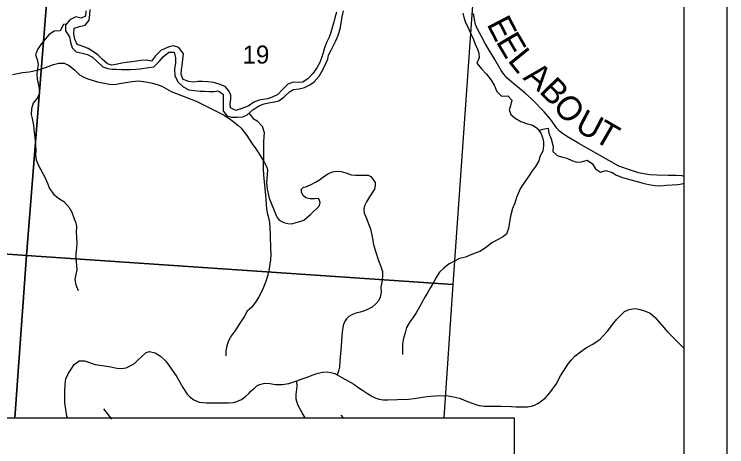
# Model space of a CAD drawing. Extents: x 0 to 34, y 0 to 22.
# Drawn here: x 28.762 to 30.417, y 18.393 to 19.396 of the extents above; entities that cross this region are included whole.
import ezdxf

# ---------------------------------------------------------------- set-up
doc = ezdxf.new("R2010")
doc.units = 0
for name, color, linetype in [('GM_X_County_Road', 7, 'Continuous'), ('GM_X_County_Road_Text', 7, 'Continuous'), ('GM_X_Major_River', 7, 'Continuous'), ('GM_X_Minor_River', 7, 'Continuous'), ('GM_X_Section', 7, 'Continuous'), ('GM_X_Section_Text', 7, 'Continuous'), ('GM_X_Township_Road', 7, 'Continuous'), ('SH_Data', 7, 'Continuous')]:
    doc.layers.add(name, color=color, linetype=linetype)

msp = doc.modelspace()

# ---------------------------------------------------------------- linework, layer by layer
at = {"layer": 'GM_X_County_Road'}
msp.add_lwpolyline([(30.3167, 19.0197), (30.313, 19.0211), (30.2994, 19.0221), (30.2811, 19.022), (30.2546, 19.023), (30.2382, 19.0237), (30.2238, 19.0261), (30.2119, 19.0284), (30.1928, 19.0342), (30.1663, 19.0437), (30.0735, 19.0965), (30.0449, 19.1136), (30.0355, 19.1192), (30.028, 19.1251), (30.0225, 19.1317), (30.0075, 19.1531), (29.9928, 19.1702), (29.9641, 19.1996), (29.9484, 19.2135), (29.922, 19.2351), (29.9071, 19.2477), (29.8991, 19.2573), (29.8929, 19.2656), (29.8782, 19.291), (29.8559, 19.3281), (29.8471, 19.3443), (29.8378, 19.3614), (29.8335, 19.3724), (29.831, 19.3846), (29.8284, 19.3983)], dxfattribs=at)
at = {"layer": 'GM_X_Major_River'}
for points in [[(29.5013, 19.3676), (29.4971, 19.3536), (29.4933, 19.3433), (29.488, 19.3323), (29.4827, 19.3187), (29.4793, 19.3065), (29.4759, 19.2955), (29.4717, 19.2841), (29.4652, 19.272), (29.4557, 19.2591), (29.4451, 19.2469), (29.4326, 19.239), (29.4231, 19.2382), (29.4102, 19.2386), (29.3973, 19.2341), (29.3844, 19.2212), (29.3741, 19.2102), (29.3597, 19.2034), (29.3502, 19.2), (29.3403, 19.1988), (29.3309, 19.1969), (29.3183, 19.192), (29.3054, 19.1833), (29.291, 19.1772), (29.277, 19.1731), (29.2644, 19.1788), (29.2637, 19.1894), (29.2652, 19.1989), (29.2652, 19.2084), (29.2607, 19.2183), (29.252, 19.2285), (29.2383, 19.2342), (29.225, 19.2377), (29.2117, 19.2392), (29.1996, 19.24), (29.1894, 19.24), (29.1776, 19.2389), (29.1673, 19.24), (29.1544, 19.245), (29.1499, 19.2563), (29.151, 19.2681), (29.1518, 19.2776), (29.1541, 19.2913), (29.1549, 19.3045), (29.1446, 19.319), (29.1321, 19.3228), (29.1219, 19.3209), (29.1124, 19.3171), (29.1029, 19.3118), (29.0904, 19.3001), (29.0812, 19.2875), (29.0683, 19.2894), (29.0558, 19.2891), (29.046, 19.2872), (29.0357, 19.2857), (29.022, 19.2846), (29.0118, 19.2831), (29.0019, 19.2808), (28.9887, 19.2781), (28.9788, 19.2812), (28.9667, 19.2918), (28.956, 19.3021), (28.9462, 19.3089), (28.934, 19.3165), (28.92, 19.3219), (28.9086, 19.326), (28.9029, 19.3382), (28.901, 19.35), (28.9011, 19.3636), (28.914, 19.3678), (28.9272, 19.3708), (28.9364, 19.3826), (28.9379, 19.3955), (28.9386, 19.4076)], [(28.9288, 19.4042), (28.9276, 19.3921), (28.9174, 19.3868), (28.9052, 19.3902), (28.8916, 19.383), (28.8813, 19.3709), (28.8813, 19.358), (28.8904, 19.3439), (28.8927, 19.3314), (28.8969, 19.3185), (28.9063, 19.3093), (28.9196, 19.3063), (28.9321, 19.3029), (28.9439, 19.2964), (28.9541, 19.2873), (28.9682, 19.2744), (28.9792, 19.2702), (28.9898, 19.2686), (28.9993, 19.2686), (29.011, 19.2679), (29.0213, 19.2679), (29.0311, 19.2682), (29.0444, 19.269), (29.0539, 19.2693), (29.0744, 19.2724), (29.0862, 19.2746), (29.0987, 19.2868), (29.1086, 19.2985), (29.1211, 19.308), (29.1336, 19.308), (29.1366, 19.2951), (29.1363, 19.2833), (29.1344, 19.2689), (29.1351, 19.2537), (29.1427, 19.2385), (29.1548, 19.2275), (29.1677, 19.221), (29.1943, 19.218), (29.2038, 19.2176), (29.214, 19.2172), (29.2261, 19.2172), (29.236, 19.2187), (29.247, 19.2111), (29.247, 19.1955), (29.2474, 19.1837), (29.2474, 19.172), (29.2557, 19.1606), (29.2667, 19.1575), (29.2796, 19.1571), (29.2929, 19.1579), (29.3028, 19.1632), (29.3164, 19.1746), (29.3301, 19.184), (29.3422, 19.1882), (29.3529, 19.1905), (29.3669, 19.1927), (29.3764, 19.1954), (29.3893, 19.2045), (29.4011, 19.2162), (29.4109, 19.2215), (29.4238, 19.2234), (29.4364, 19.2261), (29.4489, 19.2321), (29.4587, 19.2397), (29.4705, 19.2526), (29.4793, 19.2685), (29.4846, 19.2803), (29.4903, 19.2917), (29.4922, 19.3016), (29.4979, 19.3133), (29.5036, 19.3239), (29.5089, 19.3349), (29.5138, 19.3452), (29.5169, 19.3547), (29.5195, 19.3657), (29.521, 19.3763), (29.5233, 19.3904), (29.5264, 19.4044)], [(29.5104, 19.4014), (29.507, 19.3881), (29.5044, 19.3778), (29.5013, 19.3676)]]:
    msp.add_lwpolyline(points, dxfattribs=at)
at = {"layer": 'GM_X_Minor_River'}
msp.add_line((29.527, 18.4595), (29.521, 18.4659), dxfattribs=at)
for points in [[(29.8035, 19.3987), (29.8062, 19.3892), (29.8092, 19.3797), (29.8157, 19.3661), (29.8233, 19.3494), (29.8286, 19.3376), (29.8328, 19.327), (29.8377, 19.3153), (29.8408, 19.3058), (29.8415, 19.2952), (29.8366, 19.2826), (29.8469, 19.2698), (29.859, 19.2572), (29.87, 19.2432), (29.8764, 19.2315), (29.8825, 19.2171), (29.8939, 19.2064), (29.9083, 19.2068), (29.9177, 19.197), (29.9143, 19.1841), (29.9117, 19.1742), (29.9155, 19.1636), (29.9254, 19.1553), (29.9386, 19.1477), (29.9538, 19.142), (29.9659, 19.1386), (29.9761, 19.1321), (29.9852, 19.12), (29.989, 19.1102), (29.9909, 19.1003), (29.9909, 19.0908), (29.9894, 19.0783), (29.983, 19.0665), (29.98, 19.0563), (29.9724, 19.043), (29.9634, 19.0305), (29.955, 19.0176), (29.9452, 19.0043), (29.9377, 18.9926), (29.932, 18.9804), (29.9282, 18.9709), (29.9244, 18.958), (29.9195, 18.9455), (29.915, 18.9311), (29.9131, 18.919), (29.9116, 18.9095), (29.9101, 18.8993), (29.9056, 18.886), (29.8958, 18.8791), (29.8844, 18.8731), (29.8712, 18.8659), (29.8587, 18.8556), (29.8435, 18.8461), (29.8326, 18.8419), (29.8223, 18.8378), (29.8098, 18.8328), (29.7962, 18.8298), (29.783, 18.8226), (29.7724, 18.8169), (29.7599, 18.807), (29.7493, 18.7975), (29.7417, 18.7854), (29.7368, 18.7755), (29.7289, 18.7619), (29.7217, 18.7501), (29.7142, 18.7376), (29.7092, 18.7281), (29.7021, 18.716), (29.6953, 18.7034), (29.6877, 18.6921), (29.6809, 18.6822)], [(28.8834, 19.3733), (28.8764, 19.3726), (28.8687, 19.3577), (28.8551, 19.3573), (28.8426, 19.3485), (28.8339, 19.3387), (28.824, 19.3262), (28.8165, 19.3144), (28.8116, 19.3023), (28.8157, 19.2916), (28.8176, 19.2799), (28.8165, 19.27), (28.815, 19.2575), (28.8158, 19.2461), (28.8181, 19.2348), (28.8204, 19.2249), (28.8211, 19.2113), (28.8158, 19.2018), (28.8064, 19.1896), (28.8022, 19.1764), (28.8019, 19.1638), (28.8042, 19.1544), (28.8068, 19.1388), (28.808, 19.1293), (28.8095, 19.1168), (28.8107, 19.1035), (28.8118, 19.0922), (28.8122, 19.08), (28.8118, 19.0694), (28.8134, 19.0588), (28.8187, 19.0451), (28.8338, 19.0163), (28.8384, 19.0061), (28.8441, 18.9917), (28.8543, 18.978), (28.8676, 18.9678), (28.8771, 18.9617), (28.89, 18.9481), (28.8957, 18.9371), (28.9014, 18.9215), (28.9051, 18.9121), (28.9071, 18.9026), (28.9063, 18.8916), (28.9071, 18.8779), (28.9079, 18.8647), (28.9071, 18.8544), (28.9056, 18.8404), (28.9056, 18.829), (28.9068, 18.8142), (28.9075, 18.8028), (28.9049, 18.7922), (28.9026, 18.7808), (28.9049, 18.7683), (28.911, 18.755)], [(29.3071, 19.1668), (29.3169, 19.1546), (29.3267, 19.1489), (29.3377, 19.1368), (29.3423, 19.1216), (29.3419, 19.1121), (29.3412, 19.1004), (29.3408, 19.0894), (29.3412, 19.0761), (29.3408, 19.0613), (29.3401, 19.0484), (29.3401, 19.0363), (29.3412, 19.0241), (29.3416, 19.0143), (29.3432, 19.0006), (29.3439, 18.9912), (29.3455, 18.9767), (29.3462, 18.9669), (29.3474, 18.9551), (29.3481, 18.9453), (29.3497, 18.9354), (29.3523, 18.9244), (29.3546, 18.9134), (29.3558, 18.8998), (29.3565, 18.885), (29.3566, 18.8721), (29.3573, 18.8626), (29.3573, 18.8527), (29.3577, 18.8398), (29.357, 18.8262), (29.3559, 18.8163), (29.3536, 18.8019), (29.351, 18.7917), (29.3472, 18.7788), (29.3434, 18.7685), (29.3377, 18.7556), (29.3298, 18.7404), (29.3238, 18.7302), (29.3139, 18.7165), (29.3033, 18.7074), (29.2958, 18.6945), (29.2894, 18.6843), (29.2822, 18.6733), (29.2758, 18.6634), (29.2667, 18.6505), (29.2599, 18.6388), (29.2557, 18.6266), (29.2538, 18.6156), (29.2535, 18.6039)], [(29.9803, 19.1266), (29.9894, 19.1295), (30.0019, 19.1318), (30.0038, 19.12), (30.0091, 19.1075), (30.0133, 19.0893), (30.0129, 19.0779), (30.0228, 19.0688), (30.0353, 19.0647), (30.0451, 19.062), (30.0572, 19.0571), (30.0686, 19.0529), (30.0796, 19.0537), (30.0925, 19.0579), (30.1053, 19.0495), (30.1118, 19.0374), (30.1235, 19.0298), (30.136, 19.034), (30.1504, 19.0287), (30.1607, 19.023), (30.1747, 19.0177), (30.186, 19.0143), (30.1993, 19.0101), (30.2091, 19.0079), (30.222, 19.0044), (30.236, 19.0014), (30.2493, 18.9992), (30.2629, 18.9984), (30.2762, 18.9995), (30.2902, 19.0007), (30.3034, 19.0011), (30.3133, 19.0026), (30.3167, 19.0041)], [(29.6809, 18.6822), (29.673, 18.6697), (29.6696, 18.6568), (29.6658, 18.6446), (29.6639, 18.6306), (29.6636, 18.6166), (29.6639, 18.6067)], [(28.989, 18.4566), (28.97, 18.4808)]]:
    msp.add_lwpolyline(points, dxfattribs=at)
at = {"layer": 'GM_X_Section'}
for points in [[(27.875, 19.9199), (28.8721, 19.8598), (28.7909, 18.8364), (27.8204, 18.905)], [(29.8523, 19.7915), (29.781, 18.7691), (28.7909, 18.8364), (28.8721, 19.8598)]]:
    msp.add_lwpolyline(points, close=True, dxfattribs=at)
for points in [[(28.7433, 18.1795), (28.7165, 17.8103), (27.7492, 17.8771), (27.8204, 18.905), (28.7909, 18.8364), (28.7636, 18.4595)], [(28.7636, 18.4595), (28.7909, 18.8364), (29.781, 18.7691), (29.7594, 18.4595)]]:
    msp.add_lwpolyline(points, dxfattribs=at)
at = {"layer": 'GM_X_Township_Road'}
for points in [[(28.7583, 19.2568), (28.7817, 19.2612), (28.7969, 19.2629), (28.8157, 19.2665), (28.835, 19.2727), (28.8535, 19.2794), (28.8658, 19.2829), (28.878, 19.2824), (28.89, 19.2777), (28.9032, 19.2667), (28.9139, 19.2553), (28.924, 19.2505), (28.9331, 19.2467), (28.9557, 19.2397), (28.9838, 19.2338), (28.9959, 19.2329), (29.0066, 19.2355), (29.021, 19.238), (29.036, 19.2405), (29.0516, 19.2418), (29.062, 19.2403), (29.0715, 19.2384), (29.0795, 19.2369), (29.0945, 19.2336), (29.105, 19.2296), (29.1266, 19.2171), (29.1849, 19.1945), (29.2297, 19.1725), (29.25, 19.1624), (29.2664, 19.1503), (29.2817, 19.1387), (29.2895, 19.1317), (29.3021, 19.1148), (29.315, 19.0956), (29.3229, 19.084), (29.3332, 19.0682), (29.3433, 19.0517), (29.3488, 19.0418), (29.3501, 19.0347), (29.3493, 19.0253), (29.3476, 19.0052), (29.3493, 18.99), (29.3545, 18.9693), (29.3689, 18.9334), (29.3729, 18.9243), (29.3771, 18.9188), (29.3883, 18.9133), (29.3972, 18.9104), (29.4071, 18.9097), (29.4171, 18.9127), (29.4253, 18.9154), (29.4346, 18.9186), (29.4498, 18.9313), (29.4568, 18.9385), (29.4648, 18.9452), (29.4713, 18.9526), (29.4726, 18.9592), (29.4713, 18.9642), (29.4692, 18.9676), (29.4648, 18.9685), (29.4591, 18.9678), (29.4487, 18.9678), (29.4397, 18.9699), (29.4331, 18.9759), (29.4295, 18.9828), (29.4295, 18.9902), (29.4337, 18.9947), (29.4397, 18.9961), (29.4502, 19.0001), (29.4617, 19.0067), (29.4707, 19.0118), (29.4809, 19.0196), (29.4918, 19.027), (29.5013, 19.0308), (29.5108, 19.0325), (29.5214, 19.031), (29.532, 19.0285), (29.5455, 19.0238), (29.5546, 19.0228), (29.5637, 19.0225), (29.5736, 19.023), (29.5839, 19.0228), (29.5903, 19.0194), (29.5951, 19.0135), (29.6, 19.0061), (29.6002, 18.9985), (29.5987, 18.9904), (29.5869, 18.9729), (29.5799, 18.9613), (29.5753, 18.9518), (29.5738, 18.944), (29.5746, 18.9345), (29.5793, 18.9245), (29.5846, 18.9097), (29.5896, 18.8983), (29.5932, 18.8799), (29.5967, 18.8618), (29.6013, 18.8462), (29.6082, 18.8252), (29.6135, 18.8107), (29.6173, 18.7997), (29.6173, 18.7898), (29.6164, 18.7792), (29.6162, 18.7779), (29.6135, 18.7636), (29.6139, 18.7517), (29.6116, 18.7401), (29.6084, 18.7315), (29.6019, 18.7243), (29.5934, 18.7169), (29.5839, 18.712), (29.5759, 18.7078), (29.5658, 18.7048), (29.5558, 18.7023), (29.5474, 18.6996), (29.5391, 18.6947), (29.5334, 18.6892), (29.5288, 18.6829), (29.5258, 18.674), (29.5235, 18.6582), (29.5206, 18.6174), (29.5185, 18.592), (29.5174, 18.5773), (29.5149, 18.568), (29.5122, 18.5595)], [(28.8858, 18.4595), (28.8847, 18.4639), (28.8798, 18.4946), (28.8796, 18.5205), (28.8802, 18.538), (28.8823, 18.5501), (28.8884, 18.5631), (28.8956, 18.5751), (28.9014, 18.5835), (28.9129, 18.5917), (28.9253, 18.5917), (28.9502, 18.5837), (28.9718, 18.5802), (28.9866, 18.5783), (29.0002, 18.5751), (29.0111, 18.5744), (29.0218, 18.5755), (29.0311, 18.5803), (29.0413, 18.5862), (29.05, 18.5944), (29.0582, 18.6024), (29.0683, 18.6113), (29.0765, 18.6133), (29.0893, 18.6109), (29.1016, 18.6032), (29.1133, 18.5921), (29.1204, 18.5827), (29.1399, 18.5547), (29.1535, 18.53), (29.1636, 18.515), (29.1704, 18.5076), (29.1794, 18.5014), (29.1913, 18.4962), (29.2084, 18.4946), (29.2403, 18.4942), (29.2607, 18.4944), (29.2712, 18.4956), (29.2794, 18.4975), (29.2902, 18.5025), (29.2994, 18.509), (29.3072, 18.5162), (29.3127, 18.5224), (29.32, 18.5287), (29.3257, 18.5337), (29.3315, 18.5374), (29.3442, 18.5405), (29.3558, 18.5394), (29.3691, 18.537), (29.3846, 18.5372), (29.3998, 18.5394), (29.4183, 18.5458), (29.4283, 18.5492), (29.445, 18.5552), (29.4578, 18.5602), (29.4676, 18.5635), (29.4788, 18.5659), (29.4886, 18.5666), (29.4972, 18.5652), (29.5063, 18.5624), (29.5122, 18.5595), (29.5232, 18.5535), (29.5387, 18.5447), (29.5504, 18.5376), (29.5602, 18.5313), (29.5711, 18.5242), (29.5824, 18.5163), (29.594, 18.5094), (29.6017, 18.5056), (29.6098, 18.5032), (29.6186, 18.5015), (29.6305, 18.5013), (29.6522, 18.5023), (29.6775, 18.503), (29.6911, 18.5046), (29.7209, 18.5092), (29.7496, 18.5118), (29.7701, 18.5108), (29.782, 18.5087), (29.7965, 18.5051), (29.8149, 18.498), (29.8254, 18.4937), (29.8337, 18.4906), (29.8419, 18.4887), (29.8471, 18.4877), (29.8535, 18.4865), (29.8605, 18.4868), (29.8731, 18.4868), (29.8931, 18.487), (29.9167, 18.486), (29.9272, 18.4856), (29.9439, 18.4851), (29.9542, 18.4856), (29.9633, 18.4868), (29.9704, 18.4891), (29.9792, 18.4939), (29.9866, 18.4992), (29.995, 18.5054), (30.0057, 18.5178), (30.0203, 18.5376), (30.0307, 18.5573), (30.0427, 18.5764), (30.0491, 18.586), (30.0556, 18.5937), (30.0642, 18.6026), (30.0768, 18.6132), (30.0913, 18.6229), (30.1054, 18.6308), (30.1154, 18.6377), (30.1228, 18.6425), (30.13, 18.6501), (30.1407, 18.6618), (30.1517, 18.6761), (30.1617, 18.6888), (30.1696, 18.6969), (30.1796, 18.7062), (30.1898, 18.7112), (30.2034, 18.7131), (30.2127, 18.7119), (30.2254, 18.7083), (30.2387, 18.7024), (30.2502, 18.6926), (30.279, 18.6592), (30.3167, 18.6213)], [(29.4378, 18.4595), (29.4306, 18.4716), (29.4206, 18.4903), (29.4165, 18.5034), (29.4167, 18.5137), (29.4195, 18.5322), (29.4183, 18.5458)]]:
    msp.add_lwpolyline(points, dxfattribs=at)
at = {"layer": 'SH_Data'}
for points in [[(23.4167, 21), (30.4167, 21), (30.4167, 14), (23.4167, 14)], [(23.5167, 20.9), (30.3167, 20.9), (30.3167, 14.1), (23.5167, 14.1)], [(28.6022, 18.4595), (29.9232, 18.4595), (29.9232, 18.1795), (28.6022, 18.1795)]]:
    msp.add_lwpolyline(points, close=True, dxfattribs=at)

# ---------------------------------------------------------------- texts
at = {"layer": 'GM_X_County_Road_Text'}
for s, rotation, p in [('E', 297.2963, (29.8583, 19.3735)), ('E', 300.4335, (29.8795, 19.3328)), ('L', 309.0115, (29.9063, 19.2885)), ('A', 320.4249, (29.9417, 19.2467)), ('B', 314.1996, (29.9791, 19.216)), ('O', 308.0021, (30.0105, 19.1837)), ('U', 332.2469, (30.0613, 19.1276)), ('T', 329.933, (30.105, 19.1046))]:
    msp.add_text(s, height=0.0568, rotation=rotation, dxfattribs=at).set_placement(p)
at = {"layer": 'GM_X_Section_Text'}
msp.add_text('19', height=0.04186, rotation=0, dxfattribs=at).set_placement((29.2923, 19.2818))

doc.saveas('drawing.dxf')
